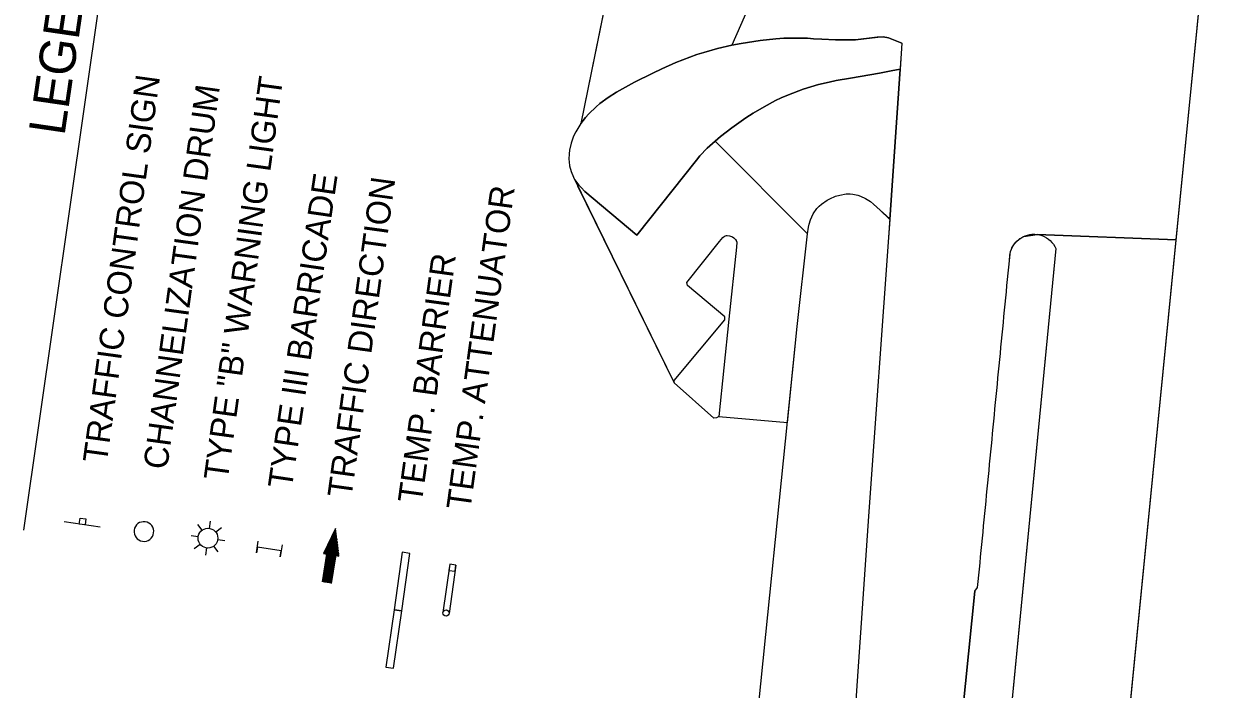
# Model space of a CAD drawing. Extents: x 1795987 to 1799689, y 243690 to 251545.
# Drawn here: x 1797501.1 to 1797887, y 249406.5 to 249621.4 of the extents above; entities that cross this region are included whole.
import ezdxf

# ---------------------------------------------------------------- set-up
doc = ezdxf.new("R2010")
doc.units = 0
for name, color, linetype in [('EP', 7, 'Continuous'), ('LEGEND', 7, 'Continuous'), ('Level 2', 7, 'Continuous'), ('Level 62', 7, 'Continuous'), ('SHADE_PRET', 7, 'Continuous')]:
    doc.layers.add(name, color=color, linetype=linetype)

# ---------------------------------------------------------------- blocks, each defined once
blk = doc.blocks.new('T21LR')
at = {"layer": 'Level 2'}
for p, q in [((0, 2), (31.5, 2)), ((0, -2), (31.5, -2))]:
    blk.add_line(p, q, dxfattribs=at)
blk.add_lwpolyline([(0, -2), (4, -2), (4, 2), (0, 2)], close=True, dxfattribs=at)
blk.add_circle((31.5, 0), 2, dxfattribs=at)

msp = doc.modelspace()

# ---------------------------------------------------------------- linework, layer by layer
at = {"layer": 'EP'}
for p, q in [((1797873.14, 249551.66), (1797886.98, 249691.77)), ((1797745.91, 249651.24), (1797729.6, 249614.5)), ((1797724.22, 249583.54), (1797754.06, 249553.61)), ((1797777.54, 249561.2), (1797777.57, 249561.23)), ((1797823.89, 249552.75), (1797828.24, 249553.37)), ((1797828.24, 249553.37), (1797828.37, 249553.34)), ((1797828.37, 249553.34), (1797829.02, 249553.22)), ((1797829.02, 249553.22), (1797829.78, 249552.99)), ((1797829.78, 249552.99), (1797830.28, 249552.78)), ((1797830.28, 249552.78), (1797830.51, 249552.69)), ((1797830.51, 249552.69), (1797831.2, 249552.32)), ((1797831.2, 249552.32), (1797831.86, 249551.88)), ((1797831.86, 249551.88), (1797832, 249551.76)), ((1797832, 249551.76), (1797832.47, 249551.37)), ((1797850.8, 249325.49), (1797873.14, 249551.66)), ((1797834.31, 249548.82), (1797815.91, 249359.06)), ((1797832.47, 249551.37), (1797833.02, 249550.81)), ((1797833.02, 249550.81), (1797833.39, 249550.34)), ((1797833.39, 249550.34), (1797833.52, 249550.19)), ((1797833.52, 249550.19), (1797833.95, 249549.52)), ((1797833.95, 249549.52), (1797834.31, 249548.82))]:
    msp.add_line(p, q, dxfattribs=at)
for points in [[(1797711.7, 249740.2), (1797680.92, 249589.25), (1797682.41, 249591.18), (1797683.49, 249592.39), (1797685.82, 249594.61), (1797687.07, 249595.64), (1797689.69, 249597.57), (1797692.46, 249599.33), (1797698.21, 249602.54), (1797704.09, 249605.52), (1797707.05, 249606.92), (1797711.53, 249608.88), (1797716.07, 249610.65), (1797718.38, 249611.46), (1797720.59, 249612.17), (1797725.06, 249613.43), (1797727.67, 249614.05)], [(1797729.6, 249614.5), (1797732.65, 249615.1), (1797738.79, 249616.05), (1797743.87, 249616.57), (1797746.41, 249616.73), (1797750.24, 249616.83), (1797754.08, 249616.74), (1797756.01, 249616.62), (1797758.67, 249616.42), (1797763.14, 249616.22), (1797769.6, 249616.28), (1797776.76, 249617.12), (1797778.53, 249617.23), (1797780.28, 249616.93), (1797784.51, 249615.19), (1797784.31, 249611.81), (1797783.97, 249606.79)], [(1797783.97, 249606.79), (1797777.34, 249605.43), (1797767.94, 249603.91), (1797763.31, 249603.07), (1797761.03, 249602.58), (1797757.66, 249601.76), (1797752.72, 249600.3), (1797747.91, 249598.51), (1797745.56, 249597.49), (1797743.7, 249596.6), (1797740.05, 249594.65), (1797736.49, 249592.52), (1797734.17, 249591), (1797729.62, 249587.8), (1797725.98, 249585.01), (1797724.22, 249583.54)], [(1797735.68, 249375.28), (1797740.64, 249424.13), (1797745.72, 249473.88), (1797750.77, 249523.67), (1797754.06, 249553.61), (1797754.38, 249555.74), (1797754.62, 249556.74), (1797755.05, 249558.14), (1797755.94, 249560.04), (1797757.11, 249561.72), (1797757.82, 249562.48), (1797758.62, 249563.19), (1797760.41, 249564.45), (1797761.28, 249564.92), (1797763.1, 249565.7), (1797764.5, 249566.11), (1797766.6, 249566.45), (1797767.89, 249566.46), (1797768.73, 249566.38), (1797770.38, 249566.02), (1797771.19, 249565.74), (1797772.79, 249564.99), (1797774.38, 249563.98), (1797775.44, 249563.17), (1797777.57, 249561.23)], [(1797754.06, 249553.61), (1797754.38, 249555.74), (1797754.62, 249556.74), (1797755.05, 249558.14), (1797755.94, 249560.04), (1797757.11, 249561.72), (1797757.82, 249562.48), (1797758.62, 249563.19), (1797760.41, 249564.45), (1797761.28, 249564.92), (1797763.1, 249565.7), (1797764.5, 249566.11), (1797766.6, 249566.45), (1797767.89, 249566.46), (1797768.73, 249566.38), (1797770.38, 249566.02), (1797771.19, 249565.74), (1797772.79, 249564.99), (1797774.38, 249563.98), (1797775.44, 249563.17), (1797780.64, 249558.43)], [(1797780.64, 249558.43), (1797780.23, 249552.43), (1797773.86, 249463.9), (1797767.65, 249373.13), (1797767.37, 249370.53)], [(1797727.35, 249526.78), (1797715.33, 249536.89), (1797715.13, 249537.81), (1797725.68, 249551.14), (1797726.77, 249552.38), (1797727.3, 249552.78), (1797727.88, 249553), (1797728.19, 249553.03), (1797728.91, 249552.95), (1797729.88, 249552.56), (1797730.32, 249552.27), (1797730.86, 249551.75), (1797731.04, 249551.46), (1797731.22, 249550.83), (1797731.14, 249549.3), (1797728.72, 249526.01), (1797725.49, 249494.54), (1797724.72, 249494.11), (1797723.88, 249494.06), (1797711.05, 249505.41), (1797710.99, 249506.18), (1797727.39, 249525.78), (1797727.35, 249526.78)], [(1797801.03, 249367.82), (1797808.16, 249438.14), (1797809.02, 249439.31), (1797809.21, 249441.3), (1797809.41, 249443.3), (1797809.6, 249445.29), (1797809.79, 249447.28), (1797809.99, 249449.27), (1797810.18, 249451.26), (1797810.37, 249453.25), (1797810.57, 249455.24), (1797810.76, 249457.23), (1797810.95, 249459.22), (1797811.15, 249461.21), (1797811.34, 249463.2), (1797811.53, 249465.19), (1797811.72, 249467.18), (1797811.92, 249469.17), (1797812.11, 249471.16), (1797812.3, 249473.16), (1797812.5, 249475.15), (1797812.69, 249477.14), (1797812.88, 249479.13), (1797813.08, 249481.12), (1797813.27, 249483.11), (1797813.46, 249485.1), (1797813.66, 249487.09), (1797813.85, 249489.08), (1797814.04, 249491.07), (1797814.23, 249493.06), (1797814.43, 249495.05), (1797814.62, 249497.04), (1797814.81, 249499.03), (1797815.01, 249501.02), (1797815.2, 249503.01), (1797815.39, 249505.01), (1797815.59, 249507), (1797815.78, 249508.99), (1797815.97, 249510.98), (1797816.16, 249512.97), (1797816.36, 249514.96), (1797816.55, 249516.95), (1797816.74, 249518.94), (1797816.94, 249520.93), (1797817.13, 249522.92), (1797817.32, 249524.91), (1797817.52, 249526.9), (1797817.71, 249528.89), (1797817.9, 249530.88), (1797818.1, 249532.87), (1797818.29, 249534.87), (1797818.48, 249536.86), (1797818.67, 249538.85), (1797818.87, 249540.84), (1797819.06, 249542.83), (1797819.25, 249544.82), (1797819.48, 249547.11), (1797819.67, 249547.88), (1797819.93, 249548.62), (1797820.28, 249549.34), (1797820.69, 249550.01), (1797821.17, 249550.64), (1797821.7, 249551.22), (1797822.3, 249551.75), (1797822.94, 249552.21), (1797823.89, 249552.75)]]:
    msp.add_lwpolyline(points, dxfattribs=at)
at = {"layer": 'LEGEND'}
for p, q in [((1797501.08, 249457.88), (1797556.62, 249845.43)), ((1797525.67, 249458.85), (1797514.09, 249460.51)), ((1797558.59, 249457.81), (1797557.21, 249459.66)), ((1797560.96, 249458.42), (1797561.29, 249460.71)), ((1797557.35, 249455.71), (1797555.06, 249456.04)), ((1797564.91, 249458.56), (1797563.07, 249457.17)), ((1797601.64, 249458.41), (1797597.82, 249450.25)), ((1797602.77, 249449.47), (1797601.64, 249458.41)), ((1797556.1, 249451.96), (1797557.95, 249453.34)), ((1797560.06, 249452.09), (1797559.73, 249449.81)), ((1797563.81, 249450.85), (1797562.42, 249452.7)), ((1797563.67, 249454.8), (1797565.96, 249454.48)), ((1797598.75, 249450.1), (1797597.35, 249441.13)), ((1797597.82, 249450.25), (1797598.75, 249450.1)), ((1797600.43, 249440.65), (1797601.84, 249449.62)), ((1797601.84, 249449.62), (1797602.77, 249449.47))]:
    msp.add_line(p, q, dxfattribs=at)
for points in [[(1797518.91, 249459.82), (1797519.19, 249461.75), (1797521.12, 249461.47), (1797520.84, 249459.54)], [(1797625.73, 249450.35), (1797623.26, 249450.71), (1797620.6, 249432.15), (1797623.07, 249431.79)], [(1797623.07, 249431.79), (1797620.6, 249432.15), (1797617.94, 249413.59), (1797620.42, 249413.23)]]:
    msp.add_lwpolyline(points, close=True, dxfattribs=at)
for points in [[(1797600.3, 249455.55), (1797598.02, 249441.02)], [(1797600.7, 249456.4), (1797598.28, 249440.98)], [(1797601.09, 249457.24), (1797598.54, 249440.94)], [(1797601.49, 249458.09), (1797598.79, 249440.9)], [(1797601.71, 249457.83), (1797599.05, 249440.86)], [(1797601.83, 249456.9), (1797599.31, 249440.82)], [(1797601.95, 249455.97), (1797599.56, 249440.78)], [(1797584.46, 249453.09), (1797583.84, 249449.24), (1797584.15, 249451.17), (1797576.45, 249452.4), (1797576.14, 249450.48), (1797576.75, 249454.33)], [(1797599.51, 249453.85), (1797597.51, 249441.1)], [(1797599.9, 249454.7), (1797597.77, 249441.06)], [(1797598.72, 249452.16), (1797598.4, 249450.16)], [(1797599.11, 249453), (1797598.66, 249450.12)], [(1797602.06, 249455.04), (1797599.82, 249440.74)], [(1797602.18, 249454.11), (1797600.08, 249440.7)], [(1797602.3, 249453.19), (1797600.33, 249440.66)], [(1797602.42, 249452.26), (1797602, 249449.59)], [(1797602.53, 249451.33), (1797602.25, 249449.55)], [(1797597.92, 249450.46), (1797597.89, 249450.24)], [(1797598.32, 249451.31), (1797598.15, 249450.2)], [(1797602.65, 249450.4), (1797602.51, 249449.51)]]:
    msp.add_lwpolyline(points, dxfattribs=at)
msp.add_circle((1797560.51, 249455.26), 3.19, dxfattribs=at)
for start, end in [(81.8439, 261.8439), (261.8439, 81.8439)]:
    msp.add_arc((1797539.82, 249457.4), 3.18, start, end, dxfattribs=at)
at = {"layer": 'Level 62'}
for p, q in [((1797711.7, 249740.2), (1797680.92, 249589.25)), ((1797850.8, 249325.49), (1797886.98, 249691.77)), ((1797678.5, 249571.91), (1797711.05, 249505.41)), ((1797828.24, 249553.37), (1797873.14, 249551.66)), ((1797725.49, 249494.54), (1797747.61, 249492.58))]:
    msp.add_line(p, q, dxfattribs=at)
for points in [[(1797711.7, 249740.2), (1797680.92, 249589.25), (1797682.41, 249591.18), (1797683.49, 249592.39), (1797685.82, 249594.61), (1797687.07, 249595.64), (1797689.69, 249597.57), (1797692.46, 249599.33), (1797698.21, 249602.54), (1797704.09, 249605.52), (1797707.05, 249606.92), (1797711.53, 249608.88), (1797716.07, 249610.65), (1797718.38, 249611.46), (1797720.59, 249612.17), (1797725.06, 249613.43), (1797729.6, 249614.5), (1797732.65, 249615.1), (1797738.79, 249616.05), (1797743.87, 249616.57), (1797746.41, 249616.73), (1797750.24, 249616.83), (1797754.08, 249616.74), (1797756.01, 249616.62), (1797758.67, 249616.42), (1797763.14, 249616.22), (1797769.6, 249616.28), (1797776.76, 249617.12), (1797778.53, 249617.23), (1797780.28, 249616.93), (1797784.51, 249615.19), (1797784.31, 249611.81), (1797783.97, 249606.79), (1797780.63, 249558.17), (1797780.23, 249552.43), (1797773.86, 249463.9), (1797767.65, 249373.13)], [(1797801.03, 249367.82), (1797808.16, 249438.14), (1797809.02, 249439.31), (1797809.21, 249441.3), (1797809.41, 249443.3), (1797809.6, 249445.29), (1797809.79, 249447.28), (1797809.99, 249449.27), (1797810.18, 249451.26), (1797810.37, 249453.25), (1797810.57, 249455.24), (1797810.76, 249457.23), (1797810.95, 249459.22), (1797811.15, 249461.21), (1797811.34, 249463.2), (1797811.53, 249465.19), (1797811.72, 249467.18), (1797811.92, 249469.17), (1797812.11, 249471.16), (1797812.3, 249473.16), (1797812.5, 249475.15), (1797812.69, 249477.14), (1797812.88, 249479.13), (1797813.08, 249481.12), (1797813.27, 249483.11), (1797813.46, 249485.1), (1797813.66, 249487.09), (1797813.85, 249489.08), (1797814.04, 249491.07), (1797814.23, 249493.06), (1797814.43, 249495.05), (1797814.62, 249497.04), (1797814.81, 249499.03), (1797815.01, 249501.02), (1797815.2, 249503.01), (1797815.39, 249505.01), (1797815.59, 249507), (1797815.78, 249508.99), (1797815.97, 249510.98), (1797816.16, 249512.97), (1797816.36, 249514.96), (1797816.55, 249516.95), (1797816.74, 249518.94), (1797816.94, 249520.93), (1797817.13, 249522.92), (1797817.32, 249524.91), (1797817.52, 249526.9), (1797817.71, 249528.89), (1797817.9, 249530.88), (1797818.1, 249532.87), (1797818.29, 249534.87), (1797818.48, 249536.86), (1797818.67, 249538.85), (1797818.87, 249540.84), (1797819.06, 249542.83), (1797819.25, 249544.82), (1797819.48, 249547.11), (1797819.67, 249547.88), (1797819.93, 249548.62), (1797820.28, 249549.34), (1797820.69, 249550.01), (1797821.17, 249550.64), (1797821.7, 249551.22), (1797822.3, 249551.75), (1797822.94, 249552.21), (1797823.63, 249552.6), (1797824.35, 249552.92), (1797825.1, 249553.17), (1797825.88, 249553.34), (1797826.38, 249553.39), (1797827.45, 249553.44), (1797828.24, 249553.37), (1797829.02, 249553.34), (1797829.79, 249553.31), (1797873.14, 249551.66), (1797886.98, 249691.77)], [(1797784.51, 249615.19), (1797784.31, 249611.81), (1797780.23, 249552.43), (1797773.86, 249463.9), (1797767.65, 249373.13), (1797767.37, 249370.53), (1797767.17, 249369.31), (1797766.76, 249367.59), (1797765.88, 249365.23), (1797764.64, 249363.1), (1797763.87, 249362.11), (1797762.51, 249360.72), (1797761.48, 249359.87), (1797759.2, 249358.39), (1797757.35, 249357.51), (1797756.4, 249357.15), (1797754.45, 249356.63), (1797753.47, 249356.47), (1797752.01, 249356.36), (1797750.5, 249356.44), (1797749.49, 249356.59), (1797747.46, 249357.1)], [(1797784.51, 249615.19), (1797784.31, 249611.81), (1797780.23, 249552.43), (1797773.86, 249463.9), (1797767.65, 249373.13), (1797767.37, 249370.53), (1797767.17, 249369.31), (1797766.76, 249367.59), (1797765.88, 249365.23), (1797764.64, 249363.1), (1797763.87, 249362.11), (1797762.51, 249360.72), (1797761.48, 249359.87), (1797759.2, 249358.39), (1797757.35, 249357.51), (1797756.4, 249357.15), (1797754.45, 249356.63), (1797753.47, 249356.47), (1797752.01, 249356.36), (1797750.5, 249356.44), (1797749.49, 249356.59), (1797747.46, 249357.1)], [(1797780.63, 249558.17), (1797783.97, 249606.79), (1797781.05, 249606.19), (1797777.34, 249605.43), (1797767.94, 249603.91), (1797763.31, 249603.07), (1797761.03, 249602.58), (1797757.66, 249601.76), (1797752.72, 249600.3), (1797747.91, 249598.51), (1797745.56, 249597.49), (1797743.7, 249596.6), (1797740.05, 249594.65), (1797736.49, 249592.52), (1797734.17, 249591), (1797729.62, 249587.8), (1797725.98, 249585.01), (1797724.22, 249583.54), (1797721.7, 249581.22), (1797719.34, 249578.73), (1797718.23, 249577.4), (1797698.94, 249553.14), (1797682.23, 249567.3), (1797680.97, 249568.49), (1797680.23, 249569.31), (1797679.86, 249569.13), (1797710.74, 249506.05), (1797710.99, 249506.18), (1797727.39, 249525.78), (1797727.35, 249526.78), (1797715.33, 249536.89), (1797715.13, 249537.81), (1797725.68, 249551.14), (1797726.77, 249552.38), (1797727.3, 249552.78), (1797727.88, 249553), (1797728.91, 249552.95), (1797729.88, 249552.56), (1797730.86, 249551.75), (1797731.22, 249550.83), (1797731.14, 249549.3), (1797728.72, 249526.01), (1797725.49, 249494.54), (1797747.61, 249492.58), (1797750.77, 249523.67), (1797754.06, 249553.61), (1797754.38, 249555.74), (1797754.62, 249556.74), (1797755.05, 249558.14), (1797755.94, 249560.04), (1797757.11, 249561.72), (1797757.82, 249562.48), (1797758.62, 249563.19), (1797760.41, 249564.45), (1797761.28, 249564.92), (1797763.1, 249565.7), (1797764.5, 249566.11), (1797766.6, 249566.45), (1797767.89, 249566.46), (1797768.73, 249566.38), (1797770.38, 249566.02), (1797771.19, 249565.74), (1797772.79, 249564.99), (1797774.38, 249563.98), (1797775.44, 249563.17), (1797777.54, 249561.2), (1797780.63, 249558.17)], [(1797850.8, 249325.49), (1797873.14, 249551.66), (1797828.24, 249553.37), (1797828.37, 249553.34), (1797829.02, 249553.22), (1797829.78, 249552.99), (1797830.28, 249552.78), (1797830.51, 249552.69), (1797831.2, 249552.32), (1797831.86, 249551.88), (1797832, 249551.76), (1797832.47, 249551.37), (1797833.02, 249550.81), (1797833.39, 249550.34), (1797833.52, 249550.19), (1797833.95, 249549.52), (1797834.31, 249548.82), (1797815.91, 249359.06), (1797815.91, 249358.62)], [(1797808.16, 249438.14), (1797801.03, 249367.82), (1797794.26, 249305.46), (1797793.16, 249291.97), (1797793.21, 249288.18), (1797793.67, 249284.41), (1797794.52, 249280.71), (1797795.64, 249277.42), (1797797.17, 249271.08), (1797797.77, 249267.31), (1797797.98, 249263.51), (1797797.79, 249259.7), (1797797.41, 249256.99), (1797790.16, 249189.13)]]:
    msp.add_lwpolyline(points, dxfattribs=at)
at = {"layer": 'SHADE_PRET'}
for p, q in [((1797781.05, 249606.19), (1797783.97, 249606.79)), ((1797777.54, 249561.2), (1797780.63, 249558.17)), ((1797834.31, 249548.82), (1797815.91, 249359.06)), ((1797808.16, 249438.14), (1797809.02, 249439.31))]:
    msp.add_line(p, q, dxfattribs=at)
for points in [[(1797784.51, 249615.19), (1797780.28, 249616.93), (1797778.53, 249617.23), (1797776.76, 249617.12), (1797776.55, 249617.08), (1797769.6, 249616.28), (1797763.14, 249616.22), (1797758.67, 249616.42), (1797756.01, 249616.62), (1797754.08, 249616.74), (1797750.24, 249616.83), (1797746.41, 249616.73), (1797743.87, 249616.57), (1797738.79, 249616.05), (1797732.65, 249615.1), (1797729.6, 249614.5), (1797725.06, 249613.43), (1797720.59, 249612.17), (1797718.38, 249611.46), (1797716.07, 249610.65), (1797711.53, 249608.88), (1797707.05, 249606.92), (1797704.09, 249605.52), (1797698.21, 249602.54), (1797692.46, 249599.33), (1797689.69, 249597.57), (1797687.07, 249595.64), (1797685.82, 249594.61), (1797683.49, 249592.39), (1797682.41, 249591.18), (1797680.92, 249589.25), (1797679.27, 249586.52), (1797678.58, 249585.08), (1797677.76, 249582.84), (1797677.23, 249580.56), (1797677.08, 249579.4), (1797677.03, 249577.7), (1797677.08, 249576.85), (1797677.24, 249575.59), (1797677.73, 249573.72), (1797678.5, 249571.91), (1797679, 249571.02), (1797680.23, 249569.31), (1797680.97, 249568.49), (1797682.23, 249567.3), (1797698.94, 249553.14), (1797718.23, 249577.4), (1797719.34, 249578.73), (1797721.7, 249581.22), (1797724.22, 249583.54), (1797725.98, 249585.01), (1797729.62, 249587.8), (1797734.17, 249591), (1797736.49, 249592.52), (1797740.05, 249594.65), (1797743.7, 249596.6), (1797745.56, 249597.49), (1797747.91, 249598.51), (1797752.72, 249600.3), (1797757.66, 249601.76), (1797761.03, 249602.58), (1797763.31, 249603.07), (1797767.94, 249603.91), (1797777.34, 249605.43), (1797781.05, 249606.19)], [(1797784.51, 249615.19), (1797780.28, 249616.93), (1797778.53, 249617.23), (1797776.76, 249617.12), (1797776.55, 249617.08), (1797769.6, 249616.28), (1797763.14, 249616.22), (1797758.67, 249616.42), (1797756.01, 249616.62), (1797754.08, 249616.74), (1797750.24, 249616.83), (1797746.41, 249616.73), (1797743.87, 249616.57), (1797738.79, 249616.05), (1797732.65, 249615.1), (1797729.6, 249614.5), (1797725.06, 249613.43), (1797720.59, 249612.17), (1797718.38, 249611.46), (1797716.07, 249610.65), (1797711.53, 249608.88), (1797707.05, 249606.92), (1797704.09, 249605.52), (1797698.21, 249602.54), (1797692.46, 249599.33), (1797689.69, 249597.57), (1797687.07, 249595.64), (1797685.82, 249594.61), (1797683.49, 249592.39), (1797682.41, 249591.18), (1797680.92, 249589.25), (1797679.27, 249586.52), (1797678.58, 249585.08), (1797677.76, 249582.84), (1797677.23, 249580.56), (1797677.08, 249579.4), (1797677.03, 249577.7), (1797677.08, 249576.85), (1797677.24, 249575.59), (1797677.73, 249573.72), (1797678.5, 249571.91), (1797679, 249571.02), (1797680.23, 249569.31), (1797680.97, 249568.49), (1797682.23, 249567.3), (1797698.94, 249553.14), (1797718.23, 249577.4), (1797719.34, 249578.73), (1797721.7, 249581.22), (1797724.22, 249583.54), (1797725.98, 249585.01), (1797729.62, 249587.8), (1797734.17, 249591), (1797736.49, 249592.52), (1797740.05, 249594.65), (1797743.7, 249596.6), (1797745.56, 249597.49), (1797747.91, 249598.51), (1797752.72, 249600.3), (1797757.66, 249601.76), (1797761.03, 249602.58), (1797763.31, 249603.07), (1797767.94, 249603.91), (1797777.34, 249605.43), (1797781.05, 249606.19)], [(1797747.61, 249492.58), (1797750.77, 249523.67), (1797754.06, 249553.61), (1797754.38, 249555.74), (1797754.62, 249556.74), (1797755.05, 249558.14), (1797755.94, 249560.04), (1797757.11, 249561.72), (1797757.82, 249562.48), (1797758.62, 249563.19), (1797760.41, 249564.45), (1797761.28, 249564.92), (1797763.1, 249565.7), (1797764.5, 249566.11), (1797766.6, 249566.45), (1797767.89, 249566.46), (1797768.73, 249566.38), (1797770.38, 249566.02), (1797771.19, 249565.74), (1797772.79, 249564.99), (1797774.38, 249563.98), (1797775.44, 249563.17), (1797777.57, 249561.23)], [(1797819.48, 249547.11), (1797819.67, 249547.88), (1797819.93, 249548.62), (1797820.11, 249549), (1797820.28, 249549.34), (1797820.69, 249550.01), (1797821.17, 249550.64), (1797821.19, 249550.68), (1797821.7, 249551.22), (1797822.3, 249551.75), (1797822.67, 249552.01), (1797822.94, 249552.21), (1797823.63, 249552.6), (1797824.35, 249552.92), (1797824.43, 249552.95), (1797825.1, 249553.17), (1797825.88, 249553.34), (1797826.38, 249553.39), (1797826.66, 249553.43), (1797827.45, 249553.44), (1797828.24, 249553.37), (1797828.37, 249553.34), (1797829.02, 249553.22), (1797829.78, 249552.99), (1797830.28, 249552.78), (1797830.51, 249552.69), (1797831.2, 249552.32), (1797831.86, 249551.88), (1797832, 249551.76), (1797832.47, 249551.37), (1797833.02, 249550.81), (1797833.39, 249550.34), (1797833.52, 249550.19), (1797833.95, 249549.52), (1797834.31, 249548.82)], [(1797809.02, 249439.31), (1797809.21, 249441.3), (1797809.41, 249443.3), (1797809.6, 249445.29), (1797809.79, 249447.28), (1797809.99, 249449.27), (1797810.18, 249451.26), (1797810.37, 249453.25), (1797810.57, 249455.24), (1797810.76, 249457.23), (1797810.95, 249459.22), (1797811.15, 249461.21), (1797811.34, 249463.2), (1797811.53, 249465.19), (1797811.72, 249467.18), (1797811.92, 249469.17), (1797812.11, 249471.16), (1797812.3, 249473.16), (1797812.5, 249475.15), (1797812.69, 249477.14), (1797812.88, 249479.13), (1797813.08, 249481.12), (1797813.27, 249483.11), (1797813.46, 249485.1), (1797813.66, 249487.09), (1797813.85, 249489.08), (1797814.04, 249491.07), (1797814.23, 249493.06), (1797814.43, 249495.05), (1797814.62, 249497.04), (1797814.81, 249499.03), (1797815.01, 249501.02), (1797815.2, 249503.01), (1797815.39, 249505.01), (1797815.59, 249507), (1797815.78, 249508.99), (1797815.97, 249510.98), (1797816.16, 249512.97), (1797816.36, 249514.96), (1797816.55, 249516.95), (1797816.74, 249518.94), (1797816.94, 249520.93), (1797817.13, 249522.92), (1797817.32, 249524.91), (1797817.52, 249526.9), (1797817.71, 249528.89), (1797817.9, 249530.88), (1797818.1, 249532.87), (1797818.29, 249534.87), (1797818.48, 249536.86), (1797818.67, 249538.85), (1797818.87, 249540.84), (1797819.06, 249542.83), (1797819.25, 249544.82), (1797819.45, 249546.81), (1797819.48, 249547.11)]]:
    msp.add_lwpolyline(points, dxfattribs=at)

# ---------------------------------------------------------------- block references
at = {"layer": 'LEGEND', "xscale": 0.5000000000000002, "yscale": 0.5000000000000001, "rotation": -98.00678026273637}
msp.add_blockref('T21LR', (1797639.57, 249446.69), dxfattribs=at)

# ---------------------------------------------------------------- texts
at = {"layer": 'LEGEND'}
for s, height, rotation, p in [('LEGEND', 11.7, 81.6779, (1797514.15, 249585.02)), ('TRAFFIC CONTROL SIGN', 7.7999, 82.1569, (1797527.81, 249479.22)), ('TYPE "B" WARNING LIGHT', 7.7999, 82.1569, (1797566.85, 249473.62)), ('CHANNELIZATION DRUM', 7.7999, 82.1569, (1797547.3, 249477.17)), ('TYPE III BARRICADE', 7.7999, 81.6779, (1797587.54, 249470.96)), ('TRAFFIC DIRECTION', 7.7999, 82.1569, (1797606.79, 249468.03)), ('TEMP. ATTENUATOR', 7.7999, 82.1569, (1797645.19, 249464.08)), ('TEMP. BARRIER', 7.7999, 82.1569, (1797629.51, 249466.28))]:
    msp.add_text(s, height=height, rotation=rotation, dxfattribs=at).set_placement(p)

doc.saveas('drawing.dxf')
